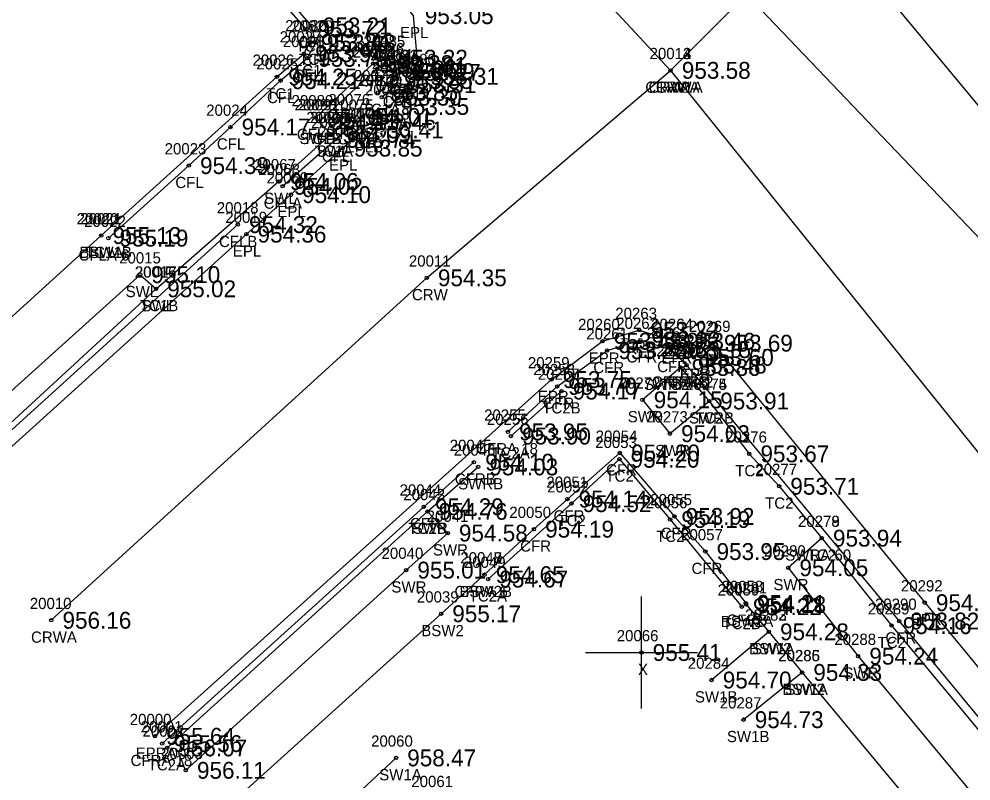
# Model space of a CAD drawing. Extents: x 1576181 to 1577685, y 1099396 to 1101490.
# Drawn here: x 1576353 to 1576437.8, y 1099543.1 to 1099611 of the extents above; entities that cross this region are included whole.
import ezdxf

# ---------------------------------------------------------------- set-up
doc = ezdxf.new("R2010")
doc.units = 0
for name, color, linetype in [('RD_DTM_BkLn1', 7, 'Continuous'), ('RD_DTM_BkLn2', 7, 'Continuous'), ('RD_EX_Conc', 7, 'Continuous'), ('RD_EX_Conc_txCode', 7, 'Continuous'), ('RD_EX_Misc', 7, 'Continuous'), ('RD_EX_Misc_txCode', 7, 'Continuous'), ('RD_EX_RailRoad', 7, 'Continuous'), ('RD_EX_Road', 7, 'Continuous'), ('RD_EX_Road_txCode', 7, 'Continuous'), ('RD_EX_TX_Conc_ELEV', 7, 'Continuous'), ('RD_EX_TX_Misc_ELEV', 7, 'Continuous'), ('RD_EX_TX_Road_ELEV', 7, 'Continuous'), ('RD_HC_Survey_ELEV', 7, 'Continuous'), ('RD_HC_Survey_txCode', 7, 'Continuous'), ('RD_SMD_Locator', 7, 'Continuous')]:
    doc.layers.add(name, color=color, linetype=linetype)

msp = doc.modelspace()

# ---------------------------------------------------------------- linework, layer by layer
at = {"layer": 'RD_DTM_BkLn1'}
for points in [[(1576411.059, 1099606.41), (1576377.326, 1099642.661), (1576337.768, 1099673.474), (1576295.749, 1099700.116), (1576252.729, 1099725.711), (1576209.228, 1099750.787)], [(1576442.606, 1099587.26), (1576417.823, 1099613.189), (1576402.198, 1099632.124), (1576392.536, 1099647.433)], [(1576355.859, 1099557.437), (1576389.322, 1099587.934), (1576411.059, 1099606.41), (1576417.823, 1099613.189)], [(1576411.059, 1099606.41), (1576442.512, 1099567.365), (1576473.98, 1099528.891), (1576505.724, 1099489.812), (1576537.103, 1099451.403), (1576568.875, 1099412.797)]]:
    msp.add_lwpolyline(points, dxfattribs=at)
at = {"layer": 'RD_DTM_BkLn2'}
for p, q in [((1576380.795, 1099600.714), (1576382.74, 1099602.306)), ((1576344.828, 1099568.202), (1576365.195, 1099586.953)), ((1576396.824, 1099573.84), (1576401.338, 1099577.851)), ((1576366.186, 1099546.067), (1576389.395, 1099567.132))]:
    msp.add_line(p, q, dxfattribs=at)
for points in [[(1576360.313, 1099591.697), (1576375.977, 1099605.821), (1576378.372, 1099607.894), (1576378.902, 1099608.893), (1576378.606, 1099610.063), (1576375.269, 1099613.86)], [(1576384.983, 1099604.442), (1576386.302, 1099605.503), (1576386.456, 1099606.309), (1576385.774, 1099606.842), (1576384.9, 1099606.536), (1576379.736, 1099601.846)], [(1576411.937, 1099579.949), (1576414.486, 1099576.959), (1576418.068, 1099572.258), (1576420.731, 1099569.371), (1576424.533, 1099564.747), (1576430.752, 1099556.958), (1576462.113, 1099519.29), (1576494.908, 1099479.626), (1576525.816, 1099442.202), (1576557.398, 1099404.072)], [(1576394.794, 1099561.105), (1576402.219, 1099567.823), (1576406.493, 1099571.776), (1576411.019, 1099566.41), (1576417.405, 1099558.642)]]:
    msp.add_lwpolyline(points, dxfattribs=at)
at = {"layer": 'RD_EX_Conc'}
for p, q in [((1576345.022, 1099567.755), (1576372.484, 1099592.673)), ((1576340.778, 1099574.008), (1576360.313, 1099591.697)), ((1576419.814, 1099556.405), (1576414.709, 1099552.116)), ((1576422.781, 1099552.791), (1576417.559, 1099548.583)), ((1576386.586, 1099545.179), (1576375.696, 1099535.084))]:
    msp.add_line(p, q, dxfattribs=at)
for points in [[(1576360.945, 1099591.467), (1576368.12, 1099597.926), (1576371.825, 1099601.361), (1576376.294, 1099605.493), (1576378.653, 1099607.482), (1576379.425, 1099608.864), (1576379.064, 1099610.368), (1576375.693, 1099614.257)], [(1576385.308, 1099604.019), (1576386.61, 1099605.132), (1576386.995, 1099606.234), (1576385.849, 1099607.492), (1576384.542, 1099607.007), (1576379.431, 1099602.211)], [(1576343.522, 1099569.964), (1576363.781, 1099588.213), (1576365.195, 1099586.953), (1576376.121, 1099596.515), (1576380.795, 1099600.714), (1576379.736, 1099601.846)], [(1576376.482, 1099596.086), (1576381.177, 1099600.259), (1576383.028, 1099601.816)], [(1576396.555, 1099574.211), (1576400.936, 1099578.265), (1576405.401, 1099581.448), (1576408.355, 1099582.386), (1576411.098, 1099581.536), (1576412.484, 1099580.157), (1576412.484, 1099580.157), (1576431.432, 1099557.367), (1576462.577, 1099519.628), (1576495.36, 1099480.143), (1576526.299, 1099442.62), (1576558.034, 1099404.431)], [(1576411.937, 1099579.949), (1576408.555, 1099577.066), (1576410.993, 1099574.055), (1576414.486, 1099576.959)], [(1576394.475, 1099561.498), (1576398.879, 1099565.547), (1576401.858, 1099568.231), (1576406.54, 1099572.333), (1576411.401, 1099566.681), (1576414.155, 1099563.556), (1576417.757, 1099558.95)], [(1576365.744, 1099546.452), (1576389.058, 1099567.543), (1576393.531, 1099571.514)], [(1576367.848, 1099544.074), (1576387.491, 1099561.904), (1576391.192, 1099565.202), (1576389.395, 1099567.132), (1576393.909, 1099571.093)], [(1576424.533, 1099564.747), (1576421.542, 1099562.114), (1576427.773, 1099554.238), (1576491.404, 1099477.631), (1576522.921, 1099439.594), (1576554.463, 1099401.183)], [(1576371.157, 1099540.455), (1576390.601, 1099558.016), (1576394.475, 1099561.498)], [(1576417.786, 1099558.83), (1576419.814, 1099556.405), (1576422.781, 1099552.791), (1576443.67, 1099527.669), (1576447.395, 1099523.041), (1576450.38, 1099519.359), (1576454.576, 1099514.356), (1576470.777, 1099494.842), (1576474.004, 1099490.994), (1576488.019, 1099473.929), (1576497.437, 1099462.536), (1576500.625, 1099458.759), (1576516.675, 1099439.273), (1576520.688, 1099434.463), (1576523.681, 1099430.77), (1576527.926, 1099425.882), (1576541.663, 1099409.22), (1576544.521, 1099405.702), (1576551.21, 1099397.688)]]:
    msp.add_lwpolyline(points, dxfattribs=at)
at = {"layer": 'RD_EX_Misc'}
for p, q in [((1576408.464, 1099549.564), (1576408.464, 1099559.564)), ((1576403.464, 1099554.564), (1576413.464, 1099554.564))]:
    msp.add_line(p, q, dxfattribs=at)
at = {"layer": 'RD_EX_RailRoad'}
msp.add_lwpolyline([(1576584.915, 1099426.469), (1576552.993, 1099465.141), (1576521.86, 1099502.626), (1576488.351, 1099543.205), (1576457.439, 1099580.524), (1576443.749, 1099596.959), (1576408.063, 1099639.915), (1576365.561, 1099691.122), (1576332.818, 1099730.472), (1576296.816, 1099773.867), (1576254.945, 1099824.298)], dxfattribs=at)
at = {"layer": 'RD_EX_Road'}
for points in [[(1576385.974, 1099603.197), (1576388.618, 1099605.879), (1576388.149, 1099611.282), (1576384.699, 1099615.456), (1576386.165, 1099616.781), (1576370.202, 1099635.027), (1576357.376, 1099647.313), (1576346.631, 1099656.319), (1576334.076, 1099664.489), (1576324.149, 1099670.375), (1576289.725, 1099690.815), (1576247.005, 1099716.046), (1576203.005, 1099742.272)], [(1576345.735, 1099566.974), (1576373.249, 1099591.824), (1576377.221, 1099595.34), (1576381.818, 1099599.483), (1576383.698, 1099601.102)], [(1576365.091, 1099547.103), (1576400.456, 1099578.873), (1576404.992, 1099582.283), (1576408.268, 1099583.268), (1576411.469, 1099582.29), (1576413.119, 1099580.849), (1576414.82, 1099582.112), (1576433.704, 1099559.004), (1576464.951, 1099521.111), (1576497.797, 1099481.911), (1576528.729, 1099444.459), (1576560.009, 1099406.61)]]:
    msp.add_lwpolyline(points, dxfattribs=at)
at = {"layer": 'RD_SMD_Locator'}
for centre in [(1576378.606, 1099610.063), (1576379.064, 1099610.368), (1576378.902, 1099608.893), (1576379.425, 1099608.864), (1576378.372, 1099607.894), (1576378.653, 1099607.482), (1576385.849, 1099607.492), (1576384.542, 1099607.007), (1576384.9, 1099606.536), (1576385.774, 1099606.842), (1576375.977, 1099605.821), (1576386.456, 1099606.309), (1576386.995, 1099606.234), (1576388.618, 1099605.879), (1576411.059, 1099606.41), (1576411.059, 1099606.41), (1576411.059, 1099606.41), (1576376.294, 1099605.493), (1576386.302, 1099605.503), (1576386.61, 1099605.132), (1576384.983, 1099604.442), (1576385.308, 1099604.019), (1576385.974, 1099603.197), (1576382.74, 1099602.306), (1576379.431, 1099602.211), (1576379.736, 1099601.846), (1576379.736, 1099601.846), (1576383.028, 1099601.816), (1576371.825, 1099601.361), (1576380.795, 1099600.714), (1576380.795, 1099600.714), (1576383.698, 1099601.102), (1576381.177, 1099600.259), (1576381.818, 1099599.483), (1576368.12, 1099597.926), (1576376.121, 1099596.515), (1576376.482, 1099596.086), (1576377.221, 1099595.34), (1576372.484, 1099592.673), (1576360.313, 1099591.697), (1576360.313, 1099591.697), (1576360.945, 1099591.467), (1576373.249, 1099591.824), (1576363.781, 1099588.213), (1576389.322, 1099587.934), (1576365.195, 1099586.953), (1576365.195, 1099586.953), (1576408.268, 1099583.268), (1576404.992, 1099582.283), (1576408.355, 1099582.386), (1576411.469, 1099582.29), (1576414.82, 1099582.112), (1576405.401, 1099581.448), (1576411.098, 1099581.536), (1576413.119, 1099580.849), (1576411.937, 1099579.949), (1576411.937, 1099579.949), (1576412.484, 1099580.157), (1576412.484, 1099580.157), (1576400.456, 1099578.873), (1576400.936, 1099578.265), (1576401.338, 1099577.851), (1576408.555, 1099577.066), (1576414.486, 1099576.959), (1576414.486, 1099576.959), (1576396.555, 1099574.211), (1576396.824, 1099573.84), (1576410.993, 1099574.055), (1576406.493, 1099571.776), (1576406.54, 1099572.333), (1576418.068, 1099572.258), (1576393.531, 1099571.514), (1576393.909, 1099571.093), (1576420.731, 1099569.371), (1576389.058, 1099567.543), (1576401.858, 1099568.231), (1576402.219, 1099567.823), (1576389.395, 1099567.132), (1576389.395, 1099567.132), (1576411.401, 1099566.681), (1576411.019, 1099566.41), (1576391.192, 1099565.202), (1576398.879, 1099565.547), (1576424.533, 1099564.747), (1576424.533, 1099564.747), (1576414.155, 1099563.556), (1576387.491, 1099561.904), (1576421.542, 1099562.114), (1576394.475, 1099561.498), (1576394.475, 1099561.498), (1576394.794, 1099561.105), (1576433.704, 1099559.004), (1576417.405, 1099558.642), (1576417.757, 1099558.95), (1576417.786, 1099558.83), (1576355.859, 1099557.437), (1576390.601, 1099558.016), (1576431.432, 1099557.367), (1576430.752, 1099556.958), (1576419.814, 1099556.405), (1576419.814, 1099556.405), (1576408.464, 1099554.564), (1576427.773, 1099554.238), (1576422.781, 1099552.791), (1576422.781, 1099552.791), (1576414.709, 1099552.116), (1576417.559, 1099548.583), (1576365.091, 1099547.103), (1576365.744, 1099546.452), (1576366.186, 1099546.067), (1576386.586, 1099545.179), (1576367.848, 1099544.074)]:
    msp.add_circle(centre, 0.15, dxfattribs=at)

# ---------------------------------------------------------------- texts
at = {"layer": 'RD_EX_Conc_txCode'}
for s, p in [('20030', (1576376.705, 1099609.893)), ('20029', (1576377.268, 1099609.864)), ('20027', (1576376.215, 1099608.894)), ('20028', (1576376.495, 1099608.482)), ('CFL', (1576377.859, 1099608.368)), ('20085', (1576383.691, 1099608.492)), ('TC1', (1576377.646, 1099608.063)), ('20087', (1576382.385, 1099608.007)), ('20088', (1576382.743, 1099607.536)), ('20086', (1576383.593, 1099607.842)), ('20084', (1576384.298, 1099607.309)), ('20026', (1576373.796, 1099606.821)), ('20025', (1576374.136, 1099606.493)), ('TC1', (1576377.941, 1099606.893)), ('CFL', (1576378.22, 1099606.864)), ('20081', (1576384.428, 1099606.503)), ('20083', (1576384.838, 1099607.234)), ('TC1', (1576377.411, 1099605.894)), ('20082', (1576384.453, 1099606.132)), ('CFL', (1576377.448, 1099605.482)), ('20077', (1576382.825, 1099605.442)), ('20078', (1576383.15, 1099605.019)), ('CFL', (1576383.337, 1099605.007)), ('CFL', (1576384.644, 1099605.492)), ('TC1', (1576384.814, 1099604.842)), ('TC1', (1576383.939, 1099604.536)), ('TC1', (1576385.495, 1099604.309)), ('CFL', (1576385.791, 1099604.234)), ('TC1', (1576375.016, 1099603.821)), ('CFL', (1576375.089, 1099603.493)), ('20089', (1576377.274, 1099603.211)), ('20076', (1576380.559, 1099603.306)), ('TC1', (1576385.341, 1099603.503)), ('CFL', (1576385.406, 1099603.132)), ('20024', (1576369.668, 1099602.361)), ('20090', (1576377.539, 1099602.846)), ('20091', (1576377.862, 1099602.846)), ('20075', (1576380.871, 1099602.816)), ('TC1A', (1576383.534, 1099602.442)), ('20070', (1576378.598, 1099601.714)), ('20071', (1576378.921, 1099601.714)), ('CFLA 18', (1576382.512, 1099602.019)), ('20072', (1576379.019, 1099601.259)), ('CFLB', (1576377.754, 1099600.211)), ('SWLB', (1576377.972, 1099599.846)), ('TC1B', (1576378.303, 1099599.846)), ('TC1B', (1576381.307, 1099600.306)), ('CFLB', (1576381.351, 1099599.816)), ('20023', (1576365.962, 1099598.926)), ('CFL', (1576370.62, 1099599.361)), ('TC1A', (1576379.346, 1099598.714)), ('SWL', (1576379.504, 1099598.714)), ('CFL', (1576379.972, 1099598.259)), ('20067', (1576373.939, 1099597.515)), ('20068', (1576374.301, 1099597.086)), ('CFL', (1576366.915, 1099595.926)), ('CFLA', (1576374.789, 1099594.086)), ('SWL', (1576374.829, 1099594.515)), ('20018', (1576370.61, 1099593.673)), ('20020', (1576358.116, 1099592.697)), ('20021', (1576358.439, 1099592.697)), ('20022', (1576358.787, 1099592.467)), ('CFLB', (1576370.807, 1099590.673)), ('BSW1B', (1576358.36, 1099589.697)), ('TC1A', (1576358.864, 1099589.697)), ('CFLA 6', (1576358.291, 1099589.467)), ('20015', (1576361.907, 1099589.213)), ('20016', (1576363.298, 1099587.953)), ('20017', (1576363.321, 1099587.953)), ('SWL', (1576362.489, 1099586.213)), ('TC1B', (1576363.762, 1099584.953)), ('SWL', (1576363.904, 1099584.953)), ('20262', (1576406.213, 1099583.386)), ('20261', (1576403.543, 1099582.448)), ('20265', (1576408.956, 1099582.536)), ('20266', (1576410.318, 1099581.157)), ('20267', (1576410.342, 1099581.157)), ('CFR', (1576407.126, 1099580.386)), ('20270', (1576409.78, 1099580.949)), ('20271', (1576410.103, 1099580.949)), ('CFR', (1576404.172, 1099579.448)), ('CFR', (1576409.869, 1099579.536)), ('20258', (1576398.818, 1099579.265)), ('20257', (1576399.219, 1099578.851)), ('20272', (1576406.437, 1099578.066)), ('SWRA 60', (1576408.685, 1099577.949)), ('CFRA 42', (1576409.381, 1099578.157)), ('TC2A', (1576410.205, 1099577.949)), ('CFRB', (1576410.783, 1099578.157)), ('20274', (1576412.367, 1099577.959)), ('20275', (1576412.367, 1099577.959)), ('CFR', (1576399.708, 1099576.265)), ('20255', (1576394.437, 1099575.211)), ('TC2B', (1576399.621, 1099575.851)), ('SWR', (1576407.24, 1099575.066)), ('20256', (1576394.682, 1099574.84)), ('20273', (1576408.875, 1099575.055)), ('SWRB', (1576412.698, 1099574.959)), ('TC2', (1576413.242, 1099574.959)), ('20045', (1576391.373, 1099572.514)), ('20053', (1576404.335, 1099572.776)), ('20054', (1576404.382, 1099573.333)), ('20276', (1576415.926, 1099573.258)), ('20046', (1576391.728, 1099572.093)), ('CFRA 18', (1576393.736, 1099572.211)), ('TC2A', (1576395.092, 1099571.84)), ('SWR', (1576409.678, 1099572.055)), ('CFR', (1576405.311, 1099570.333)), ('TC2', (1576416.824, 1099570.258)), ('20277', (1576418.613, 1099570.371)), ('CFRB', (1576391.83, 1099569.514)), ('20051', (1576399.984, 1099569.231)), ('TC2', (1576405.249, 1099569.776)), ('20044', (1576386.9, 1099568.543)), ('SWRB', (1576392.122, 1099569.093)), ('20052', (1576400.061, 1099568.823)), ('20042', (1576387.237, 1099568.132)), ('20043', (1576387.237, 1099568.132)), ('20055', (1576409.244, 1099567.681)), ('20056', (1576408.837, 1099567.41)), ('TC2', (1576419.487, 1099567.371)), ('20041', (1576389.318, 1099566.202)), ('20050', (1576396.682, 1099566.547)), ('CFR', (1576400.629, 1099566.231)), ('TC2', (1576400.975, 1099565.823)), ('20278', (1576422.415, 1099565.747)), ('20279', (1576422.415, 1099565.747)), ('TC2B', (1576387.678, 1099565.132)), ('CFR', (1576387.829, 1099565.543)), ('SWR', (1576388.08, 1099565.132)), ('TC2', (1576409.774, 1099564.41)), ('CFR', (1576410.173, 1099564.681)), ('20057', (1576411.997, 1099564.556)), ('SWR', (1576389.877, 1099563.202)), ('CFR', (1576397.651, 1099563.547)), ('20040', (1576385.294, 1099562.904)), ('20047', (1576392.318, 1099562.498)), ('20048', (1576392.318, 1099562.498)), ('20280', (1576419.385, 1099563.114)), ('SWRA 60', (1576421.281, 1099562.747)), ('TC2', (1576423.289, 1099562.747)), ('20049', (1576392.636, 1099562.105)), ('CFR', (1576412.926, 1099561.556)), ('SWR', (1576386.176, 1099559.904)), ('20058', (1576415.6, 1099559.95)), ('20281', (1576415.951, 1099559.83)), ('SWR', (1576420.227, 1099560.114)), ('20039', (1576388.444, 1099559.016)), ('CFRA 6', (1576391.798, 1099559.498)), ('BSW2B', (1576392.239, 1099559.498)), ('TC2A', (1576393.062, 1099559.105)), ('20059', (1576415.248, 1099559.642)), ('20290', (1576429.274, 1099558.367)), ('20282', (1576417.695, 1099557.405)), ('20283', (1576417.695, 1099557.405)), ('20289', (1576428.634, 1099557.958)), ('BSW2A', (1576415.534, 1099556.83)), ('TC2B', (1576415.689, 1099556.642)), ('CFRB', (1576416.056, 1099556.95)), ('BSW2', (1576388.837, 1099556.016)), ('20288', (1576425.654, 1099555.238)), ('TC2', (1576429.508, 1099554.958)), ('CFR', (1576430.203, 1099555.367)), ('BSW2', (1576418.05, 1099554.405)), ('SW1A', (1576418.317, 1099554.405)), ('20284', (1576412.59, 1099553.116)), ('20286', (1576420.639, 1099553.791)), ('20285', (1576420.663, 1099553.791)), ('SWR', (1576426.458, 1099552.238)), ('BSW2', (1576421.017, 1099550.791)), ('SW1A', (1576421.285, 1099550.791)), ('SW1B', (1576413.228, 1099550.116)), ('20287', (1576415.441, 1099549.583)), ('20001', (1576363.83, 1099547.452)), ('20002', (1576363.989, 1099547.067)), ('SW1B', (1576416.079, 1099546.583)), ('20060', (1576384.366, 1099546.179)), ('20003', (1576365.651, 1099545.074)), ('CFRA 18', (1576362.925, 1099544.452)), ('TC2A', (1576364.454, 1099544.067)), ('SW1A', (1576385.09, 1099543.179)), ('20061', (1576387.949, 1099542.582))]:
    msp.add_text(s, height=1, dxfattribs=at).set_placement(p)
at = {"layer": 'RD_EX_Misc_txCode'}
for s, p in [('20066', (1576406.259, 1099555.564)), ('X', (1576408.149, 1099552.564))]:
    msp.add_text(s, height=1, dxfattribs=at).set_placement(p)
at = {"layer": 'RD_EX_Road_txCode'}
for s, p in [('EPL', (1576386.945, 1099609.282)), ('20080', (1576386.421, 1099606.879)), ('20079', (1576383.817, 1099604.197)), ('EPL', (1576387.413, 1099603.879)), ('20074', (1576381.54, 1099602.102)), ('EPLA', (1576384.281, 1099601.197)), ('20073', (1576379.661, 1099600.483)), ('EPLB', (1576382.02, 1099599.102)), ('EPL', (1576380.614, 1099597.483)), ('20069', (1576375.04, 1099596.34)), ('EPL', (1576376.017, 1099593.34)), ('20019', (1576371.375, 1099592.824)), ('EPL', (1576372.044, 1099589.824)), ('20263', (1576406.126, 1099584.268)), ('20260', (1576402.811, 1099583.283)), ('20264', (1576409.328, 1099583.29)), ('20269', (1576412.678, 1099583.112)), ('20268', (1576410.978, 1099581.849)), ('EPR', (1576407.039, 1099581.268)), ('EPR', (1576403.764, 1099580.283)), ('EPR', (1576410.241, 1099580.29)), ('20259', (1576398.338, 1099579.873)), ('EPR', (1576413.591, 1099580.112)), ('EPR', (1576411.891, 1099578.849)), ('EPR', (1576399.228, 1099576.873)), ('20292', (1576431.586, 1099560.004)), ('EPR', (1576432.476, 1099557.004)), ('20000', (1576362.855, 1099548.103)), ('EPRA', (1576363.375, 1099545.103))]:
    msp.add_text(s, height=1, dxfattribs=at).set_placement(p)
at = {"layer": 'RD_EX_TX_Conc_ELEV'}
for s, p in [('953.21', (1576380.064, 1099609.618)), ('953.72', (1576379.606, 1099609.313)), ('953.84', (1576379.902, 1099608.143)), ('953.43', (1576380.425, 1099608.114)), ('953.94', (1576379.372, 1099607.144)), ('953.75', (1576379.653, 1099606.732)), ('953.28', (1576385.542, 1099606.257)), ('953.81', (1576386.774, 1099606.092)), ('953.22', (1576386.849, 1099606.742)), ('953.86', (1576385.9, 1099605.786)), ('953.79', (1576387.456, 1099605.559)), ('953.27', (1576387.995, 1099605.484)), ('954.25', (1576376.977, 1099605.071)), ('954.21', (1576377.294, 1099604.743)), ('953.85', (1576387.302, 1099604.753)), ('953.31', (1576387.61, 1099604.382)), ('953.85', (1576385.983, 1099603.692)), ('953.30', (1576386.308, 1099603.269)), ('954.14', (1576380.431, 1099601.461)), ('954.13', (1576380.736, 1099601.096)), ('954.13', (1576380.736, 1099601.096)), ('954.01', (1576383.74, 1099601.556)), ('953.45', (1576384.028, 1099601.066)), ('954.17', (1576372.825, 1099600.611)), ('954.09', (1576381.795, 1099599.964)), ('954.09', (1576381.795, 1099599.964)), ('953.74', (1576382.177, 1099599.509)), ('954.39', (1576369.12, 1099597.176)), ('954.06', (1576377.121, 1099595.765)), ('954.02', (1576377.482, 1099595.336)), ('954.32', (1576373.484, 1099591.923)), ('955.13', (1576361.313, 1099590.947)), ('955.13', (1576361.313, 1099590.947)), ('955.19', (1576361.945, 1099590.717)), ('955.10', (1576364.781, 1099587.463)), ('955.02', (1576366.195, 1099586.203)), ('955.02', (1576366.195, 1099586.203)), ('953.02', (1576409.355, 1099581.636)), ('953.28', (1576406.401, 1099580.698)), ('953.15', (1576412.098, 1099580.786)), ('953.86', (1576412.937, 1099579.199)), ('953.86', (1576412.937, 1099579.199)), ('953.48', (1576413.484, 1099579.407)), ('953.48', (1576413.484, 1099579.407)), ('953.70', (1576401.936, 1099577.515)), ('954.17', (1576402.338, 1099577.101)), ('954.15', (1576409.555, 1099576.316)), ('953.91', (1576415.486, 1099576.209)), ('953.91', (1576415.486, 1099576.209)), ('953.95', (1576397.555, 1099573.461)), ('953.90', (1576397.824, 1099573.09)), ('954.03', (1576411.993, 1099573.305)), ('954.20', (1576407.54, 1099571.583)), ('953.67', (1576419.068, 1099571.508)), ('954.10', (1576394.531, 1099570.764)), ('954.03', (1576394.909, 1099570.343)), ('954.20', (1576407.493, 1099571.026)), ('953.71', (1576421.731, 1099568.621)), ('954.14', (1576402.858, 1099567.481)), ('954.52', (1576403.219, 1099567.073)), ('954.29', (1576390.058, 1099566.793)), ('954.76', (1576390.395, 1099566.382)), ('954.76', (1576390.395, 1099566.382)), ('954.19', (1576412.019, 1099565.66)), ('953.92', (1576412.401, 1099565.931)), ('954.58', (1576392.192, 1099564.452)), ('954.19', (1576399.879, 1099564.797)), ('953.94', (1576425.533, 1099563.997)), ('953.94', (1576425.533, 1099563.997)), ('953.95', (1576415.155, 1099562.806)), ('955.01', (1576388.491, 1099561.154)), ('954.05', (1576422.542, 1099561.364)), ('954.65', (1576395.475, 1099560.748)), ('954.65', (1576395.475, 1099560.748)), ('954.67', (1576395.794, 1099560.355)), ('954.22', (1576418.405, 1099557.892)), ('954.21', (1576418.757, 1099558.2)), ('954.18', (1576418.786, 1099558.08)), ('955.17', (1576391.601, 1099557.266)), ('954.16', (1576431.752, 1099556.208)), ('953.82', (1576432.432, 1099556.617)), ('954.28', (1576420.814, 1099555.655)), ('954.28', (1576420.814, 1099555.655)), ('954.24', (1576428.773, 1099553.488)), ('954.33', (1576423.781, 1099552.041)), ('954.33', (1576423.781, 1099552.041)), ('954.70', (1576415.709, 1099551.366)), ('954.73', (1576418.559, 1099547.833)), ('955.56', (1576366.744, 1099545.702)), ('956.07', (1576367.186, 1099545.317)), ('958.47', (1576387.586, 1099544.429)), ('956.11', (1576368.848, 1099543.324))]:
    msp.add_text(s, height=1.5, dxfattribs=at).set_placement(p)
at = {"layer": 'RD_EX_TX_Misc_ELEV'}
msp.add_text('955.41', height=1.5, dxfattribs=at).set_placement((1576409.464, 1099553.814))
at = {"layer": 'RD_EX_TX_Road_ELEV'}
for s, p in [('953.05', (1576389.149, 1099610.532)), ('953.31', (1576389.618, 1099605.129)), ('953.35', (1576386.974, 1099602.447)), ('953.41', (1576384.698, 1099600.352)), ('953.85', (1576382.818, 1099598.733)), ('954.10', (1576378.221, 1099594.59)), ('954.36', (1576374.249, 1099591.074)), ('953.22', (1576409.268, 1099582.518)), ('953.45', (1576405.992, 1099581.533)), ('953.46', (1576412.469, 1099581.54)), ('953.69', (1576415.82, 1099581.362)), ('953.60', (1576414.119, 1099580.099)), ('953.75', (1576401.456, 1099578.123)), ('954.08', (1576434.704, 1099558.254)), ('955.64', (1576366.091, 1099546.353))]:
    msp.add_text(s, height=1.5, dxfattribs=at).set_placement(p)
at = {"layer": 'RD_HC_Survey_ELEV'}
for s, p in [('953.58', (1576412.059, 1099605.66)), ('953.58', (1576412.059, 1099605.66)), ('953.58', (1576412.059, 1099605.66)), ('954.35', (1576390.322, 1099587.184)), ('956.16', (1576356.859, 1099556.687))]:
    msp.add_text(s, height=1.5, dxfattribs=at).set_placement(p)
at = {"layer": 'RD_HC_Survey_txCode'}
for s, p in [('20012', (1576409.185, 1099607.41)), ('20013', (1576409.185, 1099607.41)), ('20014', (1576409.185, 1099607.41)), ('CRW2A', (1576408.807, 1099604.41)), ('CRW1A', (1576409.091, 1099604.41)), ('CRW', (1576409.744, 1099604.41)), ('20011', (1576387.732, 1099588.934)), ('CRW', (1576388.007, 1099585.934)), ('20010', (1576353.946, 1099558.437)), ('CRWA', (1576354.056, 1099555.437))]:
    msp.add_text(s, height=1, dxfattribs=at).set_placement(p)

doc.saveas('drawing.dxf')
